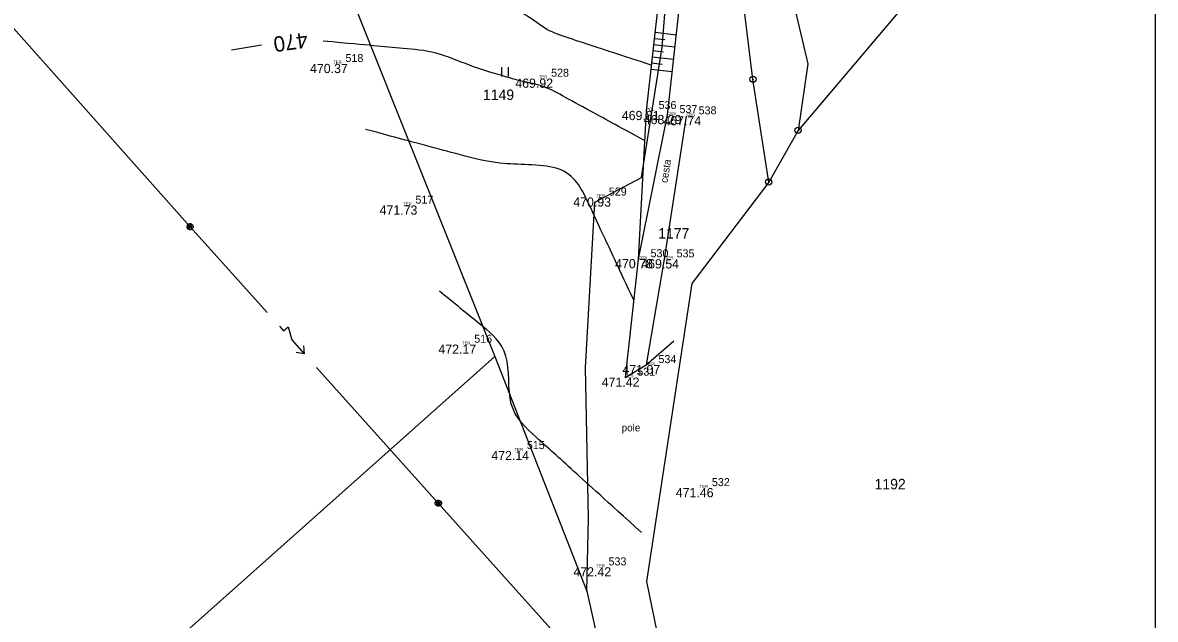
# Model space of a CAD drawing. Extents: x -604848 to -603227, y -1111879 to -1109838.
# Drawn here: x -603411.4 to -603227.3, y -1110497.4 to -1110400.4 of the extents above; entities that cross this region are included whole.
import ezdxf

# ---------------------------------------------------------------- set-up
doc = ezdxf.new("R2010")
doc.units = 0
for name, color, linetype in [('1', 7, 'Continuous'), ('10', 7, 'Continuous'), ('12', 7, 'Continuous'), ('14', 7, 'Continuous'), ('18', 7, 'Continuous'), ('19', 7, 'Continuous'), ('20', 7, 'Continuous'), ('23', 7, 'Continuous'), ('26', 7, 'Continuous'), ('28', 7, 'Continuous'), ('4', 7, 'Continuous'), ('7', 7, 'Continuous'), ('8', 7, 'Continuous'), ('9', 7, 'Continuous'), ('Default', 7, 'Continuous')]:
    doc.layers.add(name, color=color, linetype=linetype)

# ---------------------------------------------------------------- blocks, each defined once
blk = doc.blocks.new('Z601')
at = {"layer": '26'}
for p, q in [((-0.5, 0.1), (-0.4, 0.3)), ((-0.5, -0.1), (-0.5, 0.1)), ((-0.4, 0.3), (-0.3, 0.4)), ((-0.3, 0.4), (-0.1, 0.5)), ((-0.3, 0.2), (-0.3, -0.2)), ((-0.1, 0.5), (0.1, 0.5)), ((-0.1, -0.3), (-0.1, 0.3)), ((-0.1, 0.3), (0.1, 0.3)), ((0.1, 0.5), (0.3, 0.4)), ((0.1, 0.3), (0.1, -0.3)), ((0.3, 0.4), (0.4, 0.3)), ((0.3, -0.2), (0.3, 0.2)), ((0.4, 0.3), (0.5, 0.1)), ((0.5, 0.1), (0.5, -0.1)), ((-0.4, -0.3), (-0.5, -0.1)), ((-0.3, -0.4), (-0.4, -0.3)), ((-0.3, -0.2), (-0.1, -0.3)), ((-0.1, -0.5), (-0.3, -0.4)), ((0.1, -0.5), (-0.1, -0.5)), ((0.1, -0.3), (0.3, -0.2)), ((0.3, -0.4), (0.1, -0.5)), ((0.4, -0.3), (0.3, -0.4)), ((0.5, -0.1), (0.4, -0.3))]:
    blk.add_line(p, q, dxfattribs=at)
blk = doc.blocks.new('Z105')
at = {"layer": '28'}
for radius in [0.5, 0.01]:
    blk.add_circle((0, 0), radius, dxfattribs=at)
blk = doc.blocks.new('Z3060')
at = {"layer": '23'}
for p, q in [((-0.5, 0), (-0.5, 1.5)), ((0.5, 1.5), (0.5, 0))]:
    blk.add_line(p, q, dxfattribs=at)
blk = doc.blocks.new('POINT_DISPLAY')
at = {"layer": 'Default'}
blk.add_line((0, 0), (0, 0), dxfattribs=at)
blk = doc.blocks.new('Z660')
at = {"layer": '12'}
for p, q in [((-3, 0), (-2, 0)), ((-2, 0), (-2, 1)), ((-2, 1), (0, 0)), ((0, 0), (3, 0)), ((2, 0.8), (3, 0)), ((3, 0), (2, -0.8))]:
    blk.add_line(p, q, dxfattribs=at)

msp = doc.modelspace()

# ---------------------------------------------------------------- linework, layer by layer
at = {"layer": '1'}
for p, q in [((-603233.87, -1110357.15), (-603285.37, -1110417.93)), ((-603293.84, -1110364.09), (-603283.77, -1110407.11)), ((-603292.69, -1110409.63), (-603297.58, -1110369.8)), ((-603366.98, -1110373.56), (-603334.61, -1110454.66)), ((-603307.44, -1110404.43), (-603306.5, -1110392.17)), ((-603310.8, -1110425.6), (-603307.44, -1110404.43)), ((-603283.77, -1110407.11), (-603285.37, -1110417.93)), ((-603290.13, -1110426.32), (-603292.69, -1110409.63)), ((-603285.37, -1110417.93), (-603290.13, -1110426.32)), ((-603318.37, -1110429.57), (-603310.8, -1110425.6)), ((-603290.13, -1110426.32), (-603302.62, -1110442.81)), ((-603319.9, -1110456.46), (-603318.37, -1110429.57)), ((-603302.62, -1110442.81), (-603310.01, -1110491.2)), ((-603449.2, -1110556.65), (-603334.61, -1110454.66)), ((-603334.61, -1110454.66), (-603319.67, -1110492.77)), ((-603319.44, -1110480.91), (-603319.9, -1110456.46)), ((-603319.67, -1110492.77), (-603319.44, -1110480.91)), ((-603310.01, -1110491.2), (-603304.89, -1110515.93)), ((-603319.67, -1110492.77), (-603316.77, -1110505.99))]:
    msp.add_line(p, q, dxfattribs=at)
msp.add_lwpolyline([(-603227.31, -1110677.93), (-603227.31, -1109837.93), (-603821.31, -1109837.93), (-603821.31, -1110677.93), (-603227.31, -1110677.93)], dxfattribs=at)
at = {"layer": '10'}
for p, q in [((-603306.35, -1110381.61), (-603310.03, -1110414.76)), ((-603310.03, -1110414.76), (-603311.33, -1110438.84)), ((-603310.05, -1110456.04), (-603305.54, -1110452.1))]:
    msp.add_line(p, q, dxfattribs=at)
at = {"layer": '12'}
for p, q in [((-603416.05, -1110397.72), (-603384.15, -1110433.58)), ((-603384.15, -1110433.58), (-603371.64, -1110447.51)), ((-603363.62, -1110456.44), (-603343.82, -1110478.5)), ((-603343.82, -1110478.5), (-603297.1, -1110530.58))]:
    msp.add_line(p, q, dxfattribs=at)
at = {"layer": '4'}
for p, q in [((-603302.83, -1110381.2), (-603306.63, -1110415.42)), ((-603306.63, -1110415.42), (-603311.33, -1110438.84)), ((-603303.52, -1110415.62), (-603307.1, -1110438.86)), ((-603311.33, -1110438.84), (-603313.47, -1110458.09)), ((-603307.1, -1110438.86), (-603310.05, -1110456.04)), ((-603313.47, -1110458.09), (-603310.05, -1110456.04))]:
    msp.add_line(p, q, dxfattribs=at)
at = {"layer": '7'}
msp.add_line((-603372.53, -1110404.11), (-603377.4, -1110404.9), dxfattribs=at)
for points in [[(-603309.21, -1110407.33), (-603313.71, -1110405.86), (-603318.21, -1110404.39), (-603322.7, -1110402.91), (-603326.28, -1110401.74), (-603329.23, -1110399.21), (-603332.73, -1110397.72), (-603336.28, -1110396.21), (-603339.89, -1110394.57), (-603343.72, -1110394.42), (-603351.44, -1110394.1), (-603359.16, -1110393.78), (-603366.88, -1110393.46)], [(-603310.29, -1110419.59), (-603314.83, -1110417.12), (-603319.37, -1110414.64), (-603323.91, -1110412.16), (-603326.8, -1110410.58), (-603330.14, -1110410.04), (-603333.31, -1110409.09), (-603338.77, -1110407.46), (-603344.1, -1110405.09), (-603349.76, -1110404.58), (-603354.01, -1110404.2), (-603358.27, -1110403.81), (-603362.52, -1110403.43)], [(-603312.07, -1110445.52), (-603314.47, -1110440.38), (-603316.87, -1110435.23), (-603319.27, -1110430.09), (-603322.5, -1110423.16), (-603333.25, -1110423.78), (-603340.63, -1110421.8), (-603345.63, -1110420.46), (-603350.64, -1110419.12), (-603355.64, -1110417.77)], [(-603310.81, -1110483.27), (-603316.53, -1110478.09), (-603322.25, -1110472.9), (-603327.98, -1110467.72), (-603333.01, -1110463.16), (-603331.74, -1110453.76), (-603337, -1110449.47), (-603339.21, -1110447.66), (-603341.43, -1110445.86), (-603343.65, -1110444.05)]]:
    msp.add_open_spline(points, degree=3, dxfattribs=at)
at = {"layer": '8'}
for p, q in [((-603308.72, -1110402.99), (-603307.01, -1110403.18)), ((-603308.61, -1110401.99), (-603305.18, -1110402.38)), ((-603308.95, -1110404.97), (-603307.23, -1110405.17)), ((-603308.84, -1110403.98), (-603305.4, -1110404.36)), ((-603309.17, -1110406.96), (-603307.45, -1110407.15)), ((-603309.06, -1110405.97), (-603305.62, -1110406.35)), ((-603309.28, -1110407.96), (-603305.84, -1110408.34))]:
    msp.add_line(p, q, dxfattribs=at)

# ---------------------------------------------------------------- block references
at = {"layer": '12', "xscale": 0.9999990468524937, "yscale": 0.9999990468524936, "rotation": -48.08191998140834}
msp.add_blockref('Z660', (-603367.63, -1110451.98), dxfattribs=at)
at = {"layer": '18'}
for p in [(-603360.9, -1110407.12), (-603327.49, -1110409.51), (-603310.03, -1110414.76), (-603306.63, -1110415.42), (-603303.52, -1110415.62), (-603318.11, -1110428.82), (-603349.53, -1110430.13), (-603311.33, -1110438.84), (-603307.1, -1110438.86), (-603339.98, -1110452.73), (-603310.05, -1110456.04), (-603313.47, -1110458.09), (-603331.43, -1110470.01), (-603301.37, -1110476.03), (-603318.16, -1110488.91)]:
    msp.add_blockref('POINT_DISPLAY', p, dxfattribs=at)
at = {"layer": '23'}
msp.add_blockref('Z3060', (-603332.99, -1110409.18), dxfattribs=at)
at = {"layer": '26'}
for p in [(-603384.15, -1110433.58), (-603343.82, -1110478.5)]:
    msp.add_blockref('Z601', p, dxfattribs=at)
at = {"layer": '28'}
for p in [(-603292.69, -1110409.63), (-603285.37, -1110417.93), (-603290.13, -1110426.32)]:
    msp.add_blockref('Z105', p, dxfattribs=at)

# ---------------------------------------------------------------- texts
at = {"layer": '14'}
for s, p in [('1149', (-603336.56, -1110412.99)), ('1177', (-603308.09, -1110435.51)), ('1192', (-603272.93, -1110476.25))]:
    msp.add_text(s, height=1.7, dxfattribs=at).set_placement(p)
at = {"layer": '18'}
for s, p in [('TER', (-603360.9, -1110407.12)), ('TER', (-603327.49, -1110409.51)), ('POL', (-603310.03, -1110414.76)), ('CES', (-603306.63, -1110415.42)), ('CES', (-603303.52, -1110415.62)), ('TER', (-603318.11, -1110428.82)), ('TER', (-603349.53, -1110430.13)), ('CES', (-603311.33, -1110438.84)), ('CES', (-603307.1, -1110438.86)), ('TER', (-603339.98, -1110452.73)), ('CES', (-603310.05, -1110456.04)), ('CES', (-603313.47, -1110458.09)), ('TER', (-603331.43, -1110470.01)), ('TER', (-603301.37, -1110476.03)), ('TER', (-603318.16, -1110488.91))]:
    msp.add_text(s, height=0.5, dxfattribs=at).set_placement(p)
at = {"layer": '19'}
for s, p in [('518', (-603358.9, -1110406.82)), ('528', (-603325.49, -1110409.21)), ('536', (-603308.03, -1110414.46)), ('537', (-603304.63, -1110415.12)), ('538', (-603301.52, -1110415.32)), ('529', (-603316.11, -1110428.52)), ('517', (-603347.53, -1110429.83)), ('530', (-603309.33, -1110438.54)), ('535', (-603305.1, -1110438.56)), ('516', (-603337.98, -1110452.43)), ('534', (-603308.05, -1110455.74)), ('531', (-603311.47, -1110457.79)), ('515', (-603329.43, -1110469.71)), ('532', (-603299.37, -1110475.73)), ('533', (-603316.16, -1110488.61))]:
    msp.add_text(s, height=1.3, dxfattribs=at).set_placement(p)
at = {"layer": '20'}
for s, p in [('470.37 ', (-603364.66, -1110408.62)), ('469.92 ', (-603331.31, -1110411.01)), ('469.81 ', (-603314, -1110416.26)), ('468.29 ', (-603310.44, -1110416.92)), ('467.74 ', (-603307.25, -1110417.12)), ('470.93 ', (-603321.89, -1110430.32)), ('471.73 ', (-603353.36, -1110431.63)), ('470.78 ', (-603315.09, -1110440.34)), ('469.54 ', (-603310.84, -1110440.36)), ('472.17 ', (-603343.8, -1110454.23)), ('471.07 ', (-603313.9, -1110457.54)), ('471.42 ', (-603317.27, -1110459.59)), ('472.14 ', (-603335.21, -1110471.51)), ('471.46 ', (-603305.23, -1110477.53)), ('472.42 ', (-603321.87, -1110490.41))]:
    msp.add_text(s, height=1.5, dxfattribs=at).set_placement(p)
at = {"layer": '7'}
msp.add_text('470', height=2.5, rotation=188.1, dxfattribs=at).set_placement((-603365.22, -1110401.97))
at = {"layer": '9'}
msp.add_text('cesta', height=1.2, rotation=81, dxfattribs=at).set_placement((-603306.59, -1110426.53))
msp.add_text('pole', height=1.2, dxfattribs=at).set_placement((-603314.03, -1110466.83))

doc.saveas('drawing.dxf')
